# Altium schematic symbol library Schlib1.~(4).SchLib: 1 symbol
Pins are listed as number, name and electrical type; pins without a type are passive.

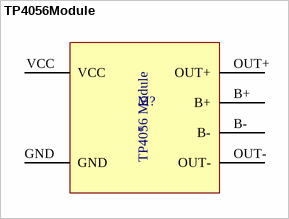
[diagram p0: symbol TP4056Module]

## TP4056Module
designator M?
TP4056 Module for managing battery charging
footprint TP4056Module
pins: B+, B-, GND, OUT+, OUT-, VCC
